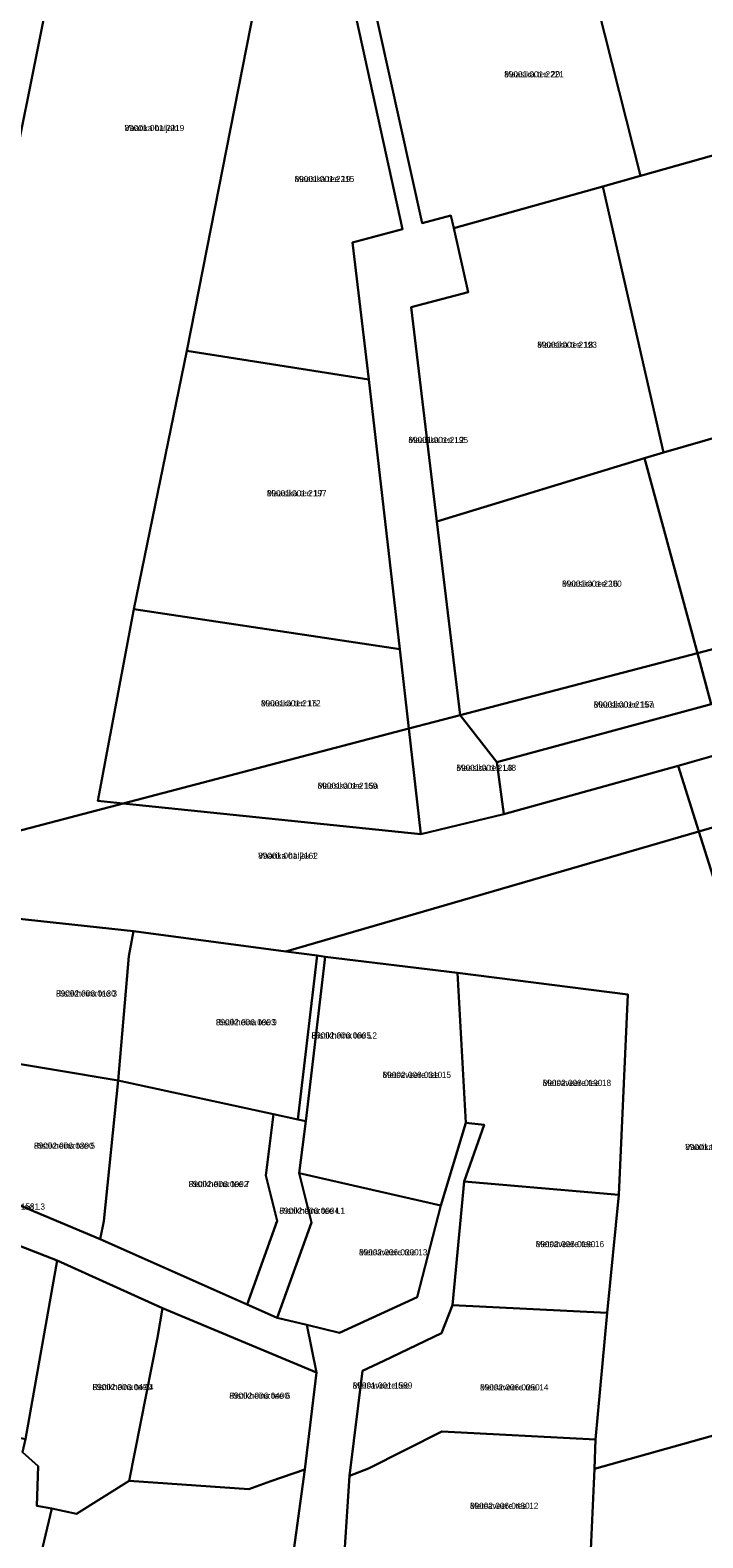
# Model space of a CAD drawing. Extents: x 526849 to 562296, y 6591741 to 6618546.
# Drawn here: x 545351.2 to 545514.7, y 6599278.2 to 6599644.6 of the extents above; entities that cross this region are included whole.
import ezdxf

# ---------------------------------------------------------------- set-up
doc = ezdxf.new("R2010")
doc.units = 0
for name, color, linetype in [('L_AADRESS', 7, 'Continuous'), ('PIIR', 7, 'Continuous'), ('TUNNUS', 7, 'Continuous')]:
    doc.layers.add(name, color=color, linetype=linetype)

msp = doc.modelspace()

# ---------------------------------------------------------------- linework, layer by layer
at = {"layer": 'PIIR'}
for points in [[(545537.22, 6599619.82), (545499.55, 6599609.18), (545483.88, 6599671.03), (545533.28, 6599684.54), (545584.92, 6599698.55), (545601.79, 6599637.97), (545558.39, 6599625.87)], [(545317.22, 6599680.17), (545358.9, 6599669.5), (545356.94, 6599659.68), (545353.41, 6599641.84), (545346.85, 6599609.12), (545343.79, 6599593.87), (545341.73, 6599594.45), (545318.31, 6599601.04), (545311.32, 6599603.01), (545296.59, 6599615.25), (545277.9, 6599630.79)], [(545499.55, 6599609.18), (545490.42, 6599606.61), (545454.15, 6599596.49), (545453.44, 6599599.51), (545446.47, 6599597.67), (545433.3, 6599657.35), (545483.88, 6599671.03)], [(545389.3, 6599566.67), (545405.74, 6599650.28), (545428.61, 6599656.14), (545441.68, 6599596.21), (545429.59, 6599592.95), (545433.49, 6599559.71)], [(545441.68, 6599596.21), (545428.61, 6599656.14), (545433.3, 6599657.35), (545446.47, 6599597.67), (545453.44, 6599599.51), (545454.15, 6599596.49), (545457.68, 6599580.88), (545443.79, 6599577.24), (545450.03, 6599525.21), (545455.71, 6599478.11), (545443.25, 6599474.84), (545441.06, 6599494.12), (545433.49, 6599559.71), (545429.59, 6599592.95)], [(545554.65, 6599556.22), (545505.11, 6599541.94), (545490.42, 6599606.61), (545499.55, 6599609.18), (545537.22, 6599619.82), (545541.84, 6599599.2), (545546.71, 6599600.23)], [(545490.42, 6599606.61), (545505.11, 6599541.94), (545500.53, 6599540.55), (545450.03, 6599525.21), (545443.79, 6599577.24), (545457.68, 6599580.88), (545454.15, 6599596.49)], [(545849.53, 6599574.65), (545901.14, 6599589.2), (545903.02, 6599577.26), (545852.53, 6599563), (545802.38, 6599548.79), (545790.67, 6599545.44), (545731.87, 6599529.05), (545675.57, 6599513.17), (545624.31, 6599498.75), (545612.97, 6599495.16), (545559.76, 6599480.37), (545508.73, 6599465.77), (545466.37, 6599454.08), (545464.6, 6599466.72), (545516.71, 6599480.8), (545565.68, 6599494.81), (545577.3, 6599497.98), (545632.75, 6599513.74), (545682.61, 6599527.68), (545736.32, 6599543), (545785.63, 6599556.86), (545797.24, 6599560.11)], [(545376.43, 6599503.88), (545389.3, 6599566.67), (545433.49, 6599559.71), (545441.06, 6599494.12)], [(545500.53, 6599540.55), (545505.11, 6599541.94), (545554.65, 6599556.22), (545563.61, 6599506.36), (545513.42, 6599493.19)], [(545450.03, 6599525.21), (545500.53, 6599540.55), (545513.42, 6599493.19), (545455.71, 6599478.11)], [(545516.71, 6599480.8), (545513.42, 6599493.19), (545563.61, 6599506.36), (545565.68, 6599494.81)], [(545367.66, 6599457.32), (545376.43, 6599503.88), (545441.06, 6599494.12), (545443.25, 6599474.84), (545373.86, 6599456.64)], [(545455.71, 6599478.11), (545513.42, 6599493.19), (545516.71, 6599480.8), (545464.6, 6599466.72)], [(545559.76, 6599480.37), (545564.54, 6599464.62), (545513.69, 6599449.89), (545508.73, 6599465.77)], [(545464.6, 6599466.72), (545466.37, 6599454.08), (545446.15, 6599449.22), (545443.25, 6599474.84), (545455.71, 6599478.11)], [(545446.15, 6599449.22), (545373.86, 6599456.64), (545443.25, 6599474.84)], [(545314.83, 6599438.78), (545315.4, 6599441.37), (545373.86, 6599456.64), (545446.15, 6599449.22), (545466.37, 6599454.08), (545508.73, 6599465.77), (545513.69, 6599449.89), (545413.33, 6599420.67), (545376.31, 6599425.64), (545341.78, 6599429.33)], [(545578.88, 6599417.67), (545526.49, 6599402.81), (545528.68, 6599436.14), (545517.63, 6599437.55), (545513.69, 6599449.89), (545564.54, 6599464.62)], [(545420.93, 6599419.68), (545413.33, 6599420.67), (545513.69, 6599449.89), (545517.63, 6599437.55), (545528.68, 6599436.14), (545526.49, 6599402.81), (545526.02, 6599366.04), (545525.08, 6599305.28), (545488.34, 6599294.98), (545488.65, 6599302.14), (545491.44, 6599332.9), (545494.26, 6599361.54), (545496.49, 6599410.25), (545455.09, 6599415.54), (545422.89, 6599419.42)], [(545338.71, 6599397.5), (545340.51, 6599423.13), (545341.78, 6599429.33), (545376.31, 6599425.64), (545375.21, 6599419.53), (545372.61, 6599389.33), (545340.58, 6599394.69)], [(545376.31, 6599425.64), (545413.33, 6599420.67), (545420.93, 6599419.68), (545416.24, 6599379.87), (545410.36, 6599381.14), (545372.61, 6599389.33), (545375.21, 6599419.53)], [(545420.93, 6599419.68), (545422.89, 6599419.42), (545418.21, 6599379.44), (545416.24, 6599379.87)], [(545416.6, 6599366.8), (545418.21, 6599379.44), (545422.89, 6599419.42), (545455.09, 6599415.54), (545457.13, 6599379.05), (545451.02, 6599359)], [(545457.13, 6599379.05), (545455.09, 6599415.54), (545496.49, 6599410.25), (545494.26, 6599361.54), (545456.68, 6599364.8), (545461.55, 6599378.59)], [(545308.96, 6599385.98), (545312.86, 6599393.85), (545318.7, 6599397.03), (545333.45, 6599390.58), (545338.71, 6599397.5), (545340.58, 6599394.69), (545331.93, 6599368.39), (545331.17, 6599366.34), (545368.2, 6599350.83), (545403.96, 6599334.94), (545411.28, 6599331.68), (545418.49, 6599329.94), (545420.77, 6599318.43), (545383.36, 6599334.01), (545357.8, 6599345.64), (545326.93, 6599357.61), (545310.42, 6599375.7), (545305.97, 6599380.3), (545304.52, 6599387.4)], [(545331.93, 6599368.39), (545340.58, 6599394.69), (545372.61, 6599389.33), (545369.16, 6599355.14), (545368.2, 6599350.83), (545331.17, 6599366.34)], [(545372.61, 6599389.33), (545410.36, 6599381.14), (545408.47, 6599366.3), (545411.25, 6599355.24), (545403.96, 6599334.94), (545368.2, 6599350.83), (545369.16, 6599355.14)], [(545410.36, 6599381.14), (545416.24, 6599379.87), (545418.21, 6599379.44), (545416.6, 6599366.8), (545419.6, 6599354.82), (545411.28, 6599331.68), (545403.96, 6599334.94), (545411.25, 6599355.24), (545408.47, 6599366.3)], [(545419.6, 6599354.82), (545416.6, 6599366.8), (545451.02, 6599359), (545445.25, 6599336.67), (545426.4, 6599328.04), (545418.49, 6599329.94), (545411.28, 6599331.68)], [(545453.84, 6599334.76), (545456.68, 6599364.8), (545494.26, 6599361.54), (545491.44, 6599332.9)], [(545321.18, 6599353.36), (545326.93, 6599357.61), (545357.8, 6599345.64), (545350.07, 6599302.23), (545313.14, 6599310.34)], [(545350.07, 6599302.23), (545357.8, 6599345.64), (545383.36, 6599334.01), (545382.2, 6599326.89), (545375.26, 6599292.03), (545362.46, 6599284.03), (545356.46, 6599285.33), (545352.86, 6599286.03), (545353.16, 6599295.63), (545349.36, 6599299.03)], [(545382.2, 6599326.89), (545383.36, 6599334.01), (545420.77, 6599318.43), (545417.96, 6599294.83), (545409.71, 6599292), (545404.36, 6599290.01), (545375.26, 6599292.03)], [(545451.22, 6599327.98), (545453.84, 6599334.76), (545491.44, 6599332.9), (545488.65, 6599302.14), (545451.26, 6599304.02), (545433.41, 6599295.06), (545428.86, 6599293.32), (545431.97, 6599318.82), (545437.18, 6599321.22)], [(545306.14, 6599271.41), (545313.14, 6599310.34), (545350.07, 6599302.23), (545349.36, 6599299.03), (545353.16, 6599295.63), (545352.86, 6599286.03), (545356.46, 6599285.33), (545352.36, 6599267.94), (545343.08, 6599269.42), (545341.66, 6599265.63)], [(545433.41, 6599295.06), (545451.26, 6599304.02), (545488.65, 6599302.14), (545488.34, 6599294.98), (545487.08, 6599266.48), (545432.6, 6599270.77), (545427.36, 6599270.92), (545428.86, 6599293.32)], [(545487.08, 6599266.48), (545488.34, 6599294.98), (545525.08, 6599305.28), (545519.03, 6599230.95), (545519.43, 6599228.95), (545522.34, 6599210.01), (545530.03, 6599169.17), (545478.96, 6599155.9), (545480.26, 6599184.73), (545481.34, 6599198.75), (545483.69, 6599225.53), (545484.3, 6599231.05), (545485.67, 6599248.7)], [(545409.71, 6599292), (545417.96, 6599294.83), (545412.96, 6599258.13), (545405.7, 6599258.56), (545363.36, 6599264.93), (545352.36, 6599267.94), (545356.46, 6599285.33), (545362.46, 6599284.03), (545375.26, 6599292.03), (545404.36, 6599290.01)]]:
    msp.add_lwpolyline(points, close=True, dxfattribs=at)
for points in [[(545405.74, 6599650.28), (545389.3, 6599566.67), (545376.43, 6599503.88), (545367.66, 6599457.32), (545373.86, 6599456.64), (545315.4, 6599441.37), (545316.99, 6599449.14), (545315.05, 6599449.64), (545318.74, 6599468.03), (545327.84, 6599513.78), (545329.66, 6599522.77), (545334.02, 6599544.69), (545338.46, 6599566.76), (545341.92, 6599584.34), (545343.79, 6599593.87), (545346.85, 6599609.12), (545353.41, 6599641.84), (545356.94, 6599659.68)], [(545412.96, 6599258.13), (545417.96, 6599294.83), (545420.77, 6599318.43), (545418.49, 6599329.94), (545426.4, 6599328.04), (545445.25, 6599336.67), (545451.02, 6599359), (545457.13, 6599379.05), (545461.55, 6599378.59), (545456.68, 6599364.8), (545453.84, 6599334.76), (545451.22, 6599327.98), (545437.18, 6599321.22), (545431.97, 6599318.82), (545428.86, 6599293.32), (545427.36, 6599270.92)]]:
    msp.add_lwpolyline(points, dxfattribs=at)

# ---------------------------------------------------------------- texts
at = {"layer": 'L_AADRESS'}
for s, p in [('Maasika tee 20', (545466.42, 6599633.11)), ('Vaarika haljak', (545374.17, 6599620.05)), ('Maasika tee 19', (545415.49, 6599607.66)), ('Maasika tee 18', (545474.45, 6599567.39)), ('Maasika tee L2', (545443.14, 6599544.25)), ('Maasika tee 17', (545408.75, 6599531.3)), ('Maasika tee 16', (545480.49, 6599509.33)), ('Maasika tee 15', (545407.31, 6599480.26)), ('Maasika tee 16a', (545488.18, 6599479.96)), ('Maasika tee L3', (545454.81, 6599464.59)), ('Maasika tee 15a', (545421.09, 6599460.23)), ('Vaarika haljak 1', (545406.63, 6599443.22)), ('Ristikheina tee 3', (545357.51, 6599409.75)), ('Ristikheina tee 9', (545396.35, 6599402.76)), ('Ristikheina tee L2', (545419.57, 6599399.55)), ('Metsaveere tee 15', (545436.87, 6599389.97)), ('Metsaveere tee 18', (545475.79, 6599388.02)), ('Ristikheina tee 5', (545352.15, 6599372.76)), ('Vaarika haljak 2', (545510.43, 6599372.44)), ('Ristikheina tee 7', (545389.73, 6599363.44)), ('Ristikheina tee L3', (545338.89, 6599357.96)), ('Ristikheina tee L1', (545411.78, 6599356.95)), ('Metsaveere tee 13', (545431.15, 6599346.86)), ('Metsaveere tee 16', (545474.09, 6599348.85)), ('Ristikheina tee 4', (545366.36, 6599314.11)), ('Metsaveere tee', (545429.61, 6599314.49)), ('Metsaveere tee 14', (545460.56, 6599314.04)), ('Ristikheina tee 6', (545399.62, 6599312.01)), ('Metsaveere tee 12', (545458.11, 6599285.25))]:
    msp.add_text(s, height=1.5, dxfattribs=at).set_placement(p)
at = {"layer": 'TUNNUS'}
for s, p in [('89001:001:2221', (545466.42, 6599633.11)), ('89001:001:2219', (545374.17, 6599620.05)), ('89001:001:2215', (545415.49, 6599607.66)), ('89001:001:2193', (545474.45, 6599567.39)), ('89001:001:2195', (545443.14, 6599544.25)), ('89001:001:2197', (545408.75, 6599531.3)), ('89001:001:2200', (545480.49, 6599509.33)), ('89001:001:2172', (545407.31, 6599480.26)), ('89001:001:2157', (545488.18, 6599479.96)), ('89001:001:2148', (545454.81, 6599464.59)), ('89001:001:2169', (545421.09, 6599460.23)), ('89001:001:2162', (545406.63, 6599443.22)), ('89002:006:0130', (545357.51, 6599409.75)), ('89002:006:0003', (545396.35, 6599402.76)), ('89002:006:0005', (545419.57, 6599399.55)), ('89002:006:0310', (545436.87, 6599389.97)), ('89002:006:0190', (545475.79, 6599388.02)), ('89002:006:0390', (545352.15, 6599372.76)), ('89001:001:2230', (545510.43, 6599372.44)), ('89002:006:0002', (545389.73, 6599363.44)), ('89001:001:1581', (545338.89, 6599357.96)), ('89002:006:0004', (545411.78, 6599356.95)), ('89002:006:0300', (545431.15, 6599346.86)), ('89002:006:0180', (545474.09, 6599348.85)), ('89002:006:0470', (545366.36, 6599314.11)), ('89001:001:1589', (545429.61, 6599314.49)), ('89002:006:0050', (545460.56, 6599314.04)), ('89002:006:0400', (545399.62, 6599312.01)), ('89002:006:0430', (545458.11, 6599285.25))]:
    msp.add_text(s, height=1.5, dxfattribs=at).set_placement(p)

doc.saveas('drawing.dxf')
